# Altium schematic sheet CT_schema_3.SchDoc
size 461 x 297 mm
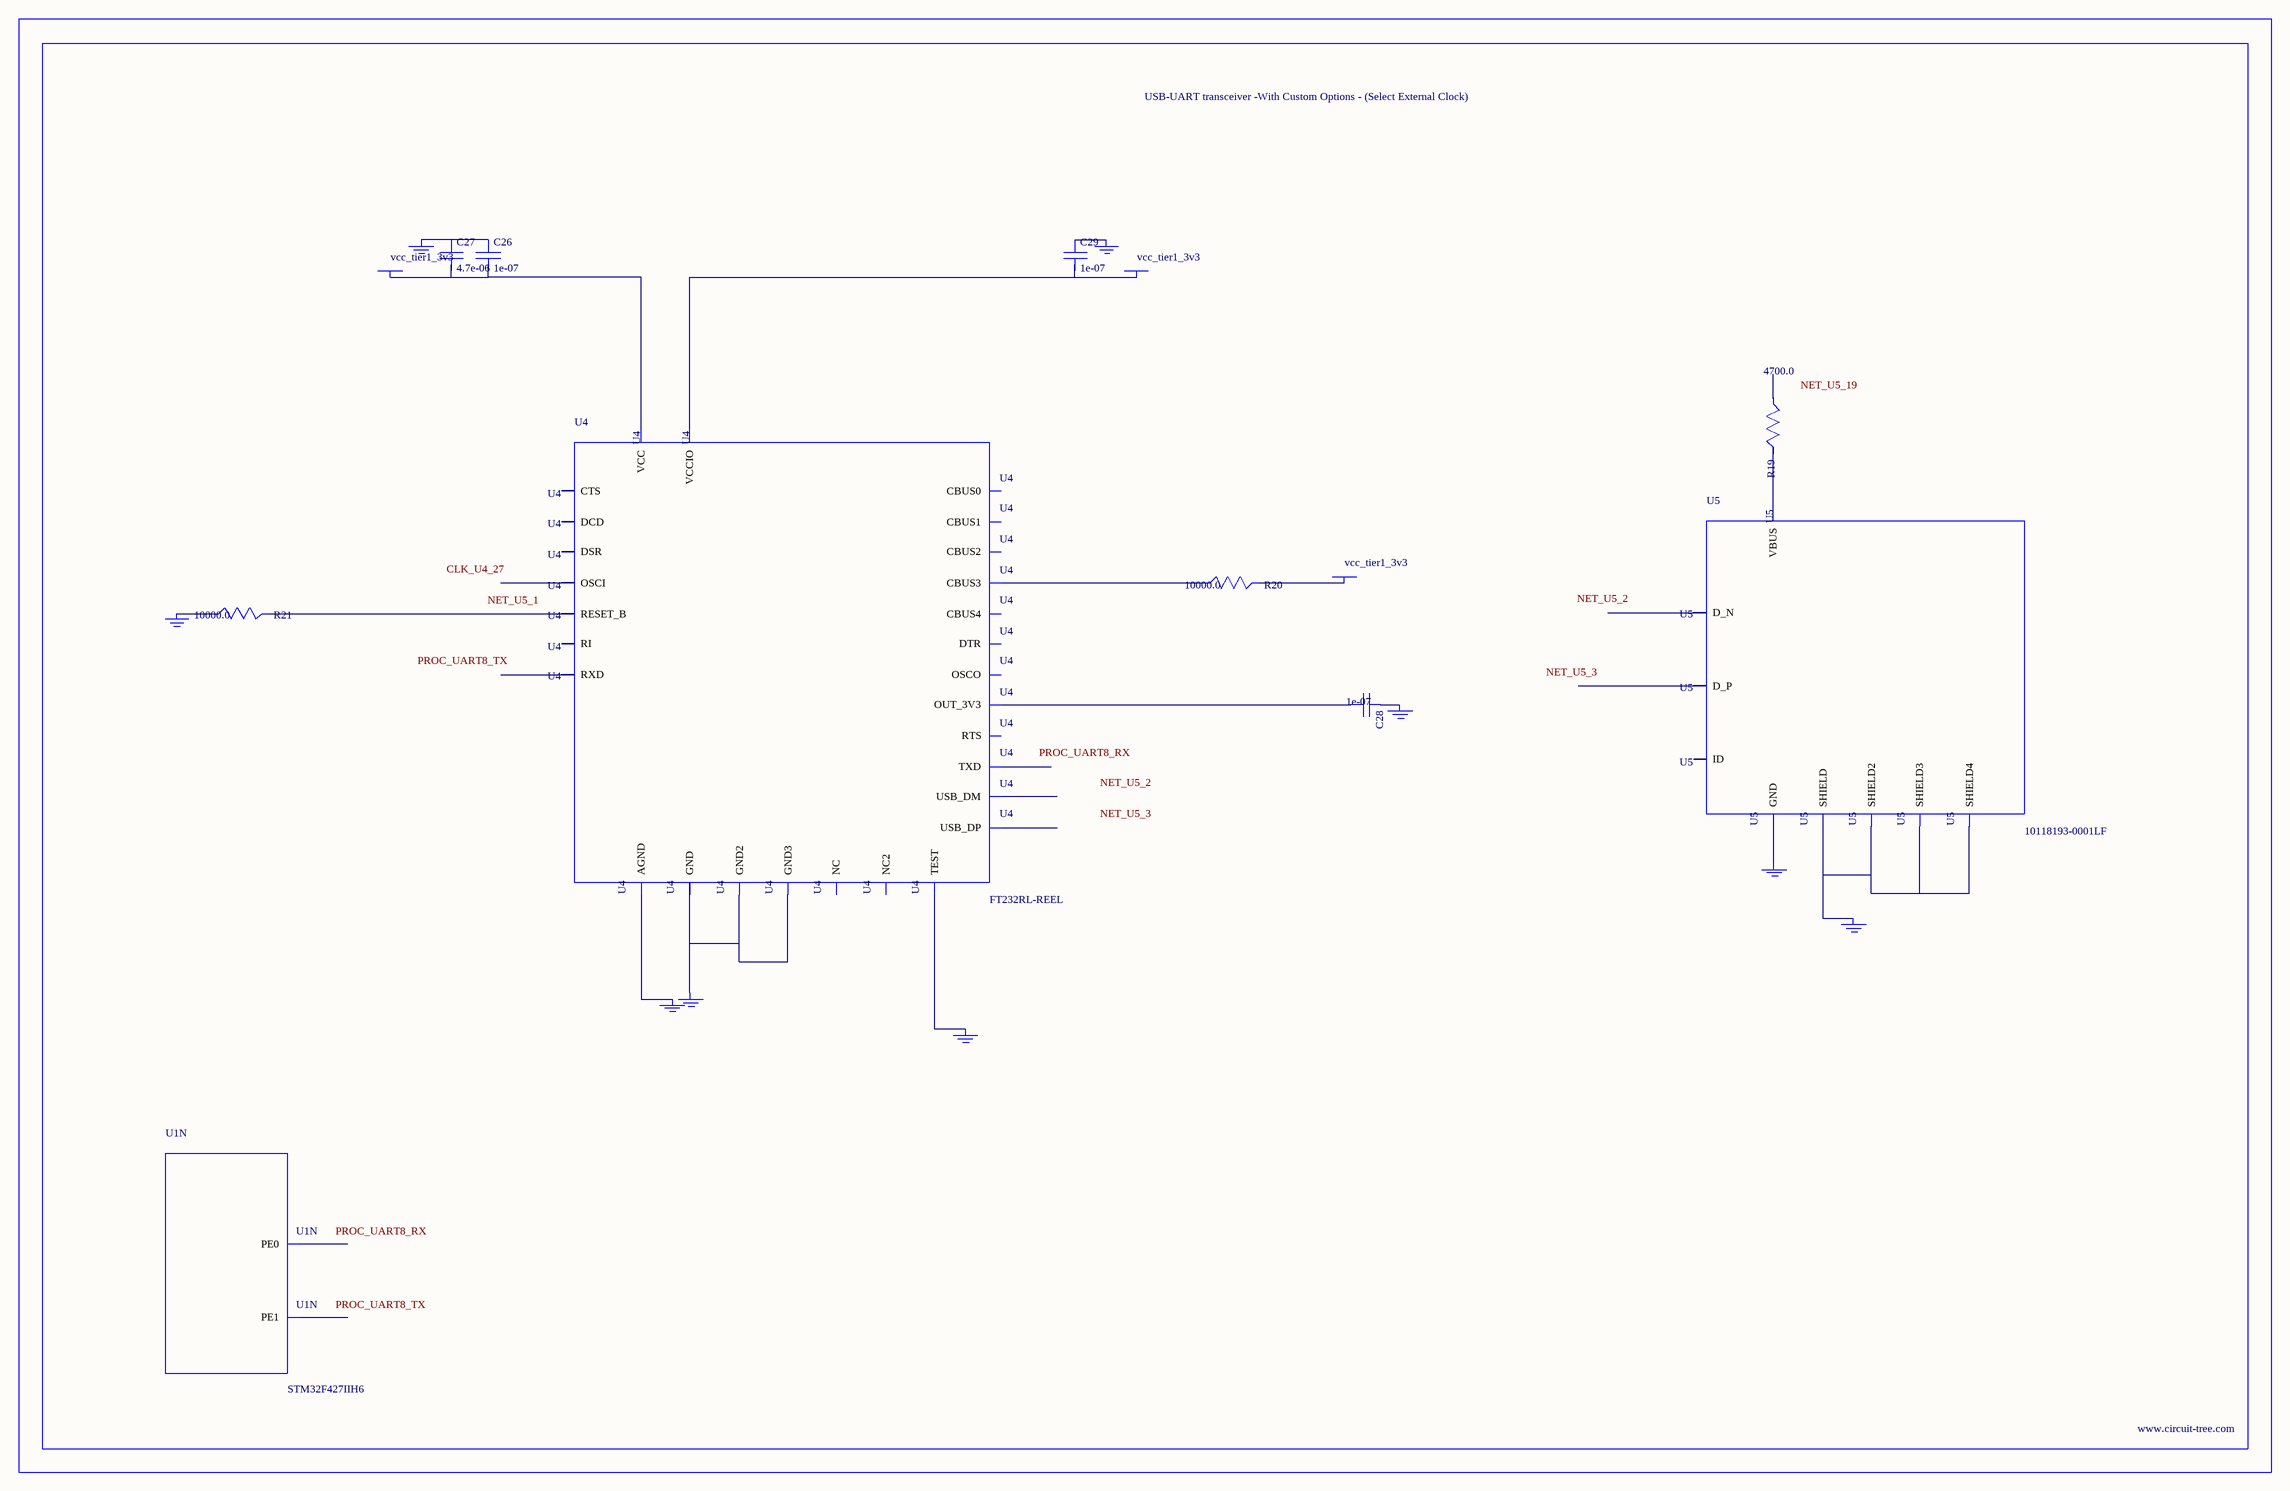
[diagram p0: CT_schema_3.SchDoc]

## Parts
BORDER2  (no value)
C26  1e-07  [C0402]
C27  4.7e-06  [C0805]
C28  1e-07  [C0402]
C29  1e-07  [C0402]
GND_INSTANCE_2_0  (no value)
GND_INSTANCE_2_1  (no value)
GND_INSTANCE_2_2  (no value)
GND_INSTANCE_2_3  (no value)
GND_INSTANCE_2_4  (no value)
GND_INSTANCE_2_5  (no value)
GND_INSTANCE_2_6  (no value)
GND_INSTANCE_2_7  (no value)
GND_INSTANCE_2_8  (no value)
POWER_INSTANCE_2_0  vcc_tier1_3v3
POWER_INSTANCE_2_1  vcc_tier1_3v3
POWER_INSTANCE_2_2  vcc_tier1_3v3
R19  4700.0  [R0603]
R20  10000.0  [R0603]
R21  10000.0  [R0603]
U1  STM32F427IIH6  [UFBGA176_25]  (part N of 17)
U4  FT232RL-REEL  [SSOP-28]
U5  10118193-0001LF  [FCI_10118193-0001LF]

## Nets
NetC26_1: C26.1 C27.1 GND_INSTANCE_2_3.0(GND)
NetC26_2: C26.2 C27.2 POWER_INSTANCE_2_2.0(PWR) U4.20(VCC)
NetC28_1: C28.1 GND_INSTANCE_2_1.0(GND)
NetC28_2: C28.2 U4.17(OUT_3V3)
NetC29_1: C29.1 GND_INSTANCE_2_0.0(GND)
NetC29_2: C29.2 POWER_INSTANCE_2_0.0(PWR) U4.4(VCCIO)
NetGND_INSTANCE_2_2_0: GND_INSTANCE_2_2.0(GND) R21.1
NetGND_INSTANCE_2_4_0: GND_INSTANCE_2_4.0(GND) U4.25(AGND)
NetGND_INSTANCE_2_5_0: GND_INSTANCE_2_5.0(GND) U4.26(TEST)
NetGND_INSTANCE_2_6_0: GND_INSTANCE_2_6.0(GND) U4.7(GND) U4.18(GND2) U4.21(GND3)
NetGND_INSTANCE_2_7_0: GND_INSTANCE_2_7.0(GND) U5.6(SHIELD) U5.7(SHIELD2) U5.8(SHIELD3) U5.9(SHIELD4)
NetGND_INSTANCE_2_8_0: GND_INSTANCE_2_8.0(GND) U5.5(GND)
NetPOWER_INSTANCE_2_1_0: POWER_INSTANCE_2_1.0(PWR) R20.2
NetR19_2: R19.2 U5.1(VBUS)
NetR20_1: R20.1 U4.14(CBUS3)
NetR21_2: R21.2 U4.19(RESET_B)

Not connected (* = marked no-connect by the designer): R19 1; U1 A3(PE1) A4(PE0); U4 1(TXD) 2(DTR) 3(RTS) 5(RXD) 6(RI) 8(NC) 9(DSR) 10(DCD) 11(CTS) 12(CBUS4) 13(CBUS2) 15(USB_DP) 16(USB_DM) 22(CBUS1) 23(CBUS0) 24(NC2) 27(OSCI) 28(OSCO); U5 2(D_N) 3(D_P) 4(ID)

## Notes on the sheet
- Labels drawn without touching a wire or pin: CLK_U4_27, NET_U5_1, NET_U5_2, NET_U5_3, NET_U5_19, PROC_UART8_RX, PROC_UART8_TX

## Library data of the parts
BORDER2 = BORDER_PAGE2
C26 C28 C29 = C0402C104K3RACTU
C27 = C0805C475K4RACTU
GND_INSTANCE_2_0-GND_INSTANCE_2_8 = GND
POWER_INSTANCE_2_0-POWER_INSTANCE_2_2 = PWR
R19 = RC0603JR-074K7L
R20 R21 = RC0603JR-0710KL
